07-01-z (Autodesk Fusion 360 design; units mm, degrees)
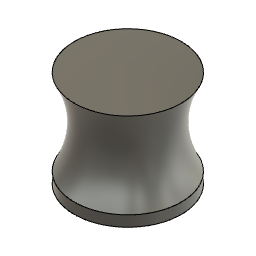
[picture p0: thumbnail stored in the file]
sketch "スケッチ1" plane through (0, 0, 0) normal (0, 1, 0) x axis (1, 0, 0)
  circle C1 centre (0, 0) radius 25
  point P1 (0, 0)
  point P2 (0, 0)
  coincident P1 P2
  dimension "d1" diameter C1 = 50
extrude "押し出し" new body sketch "スケッチ1" along normal blind 5
work_plane "作業平面1" AlongDistance 20
sketch "スケッチ2" plane through (0, 25, 0) normal (0, 1, 0) x axis (1, 0, 0)
  circle C1 centre (0, 0) radius 20
  point P1 (0, 0)
  point P2 (0, 0)
  coincident P1 P2
  dimension "d5" diameter C1 = 40
work_plane "作業平面2" AlongDistance 20
sketch "スケッチ3" plane through (0, 45, 0) normal (0, 1, 0) x axis (1, 0, 0)
  circle C1 centre (0, 0) radius 25
loft "ロフト" sketch "スケッチ2" + "スケッチ3"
